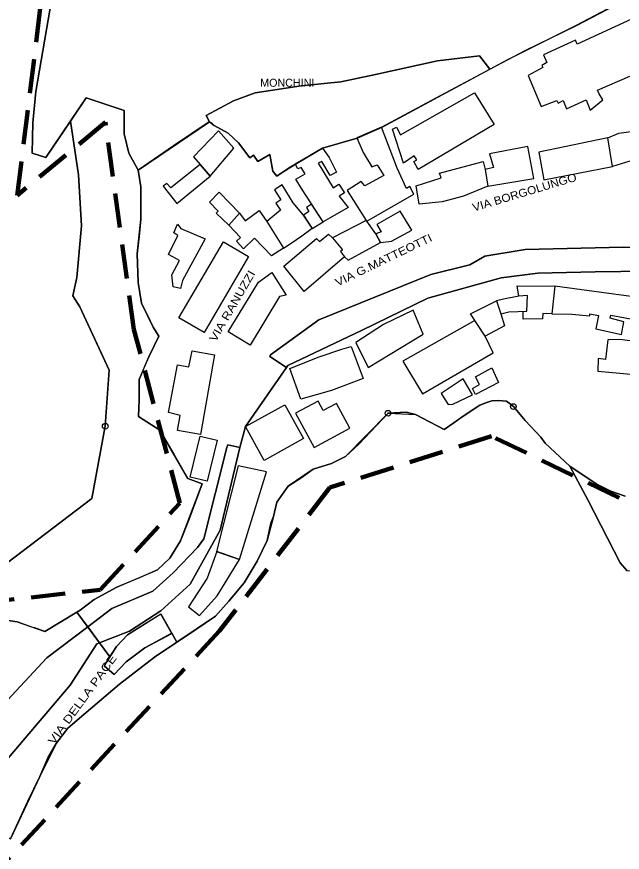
# Model space of a CAD drawing. Extents: x 654952 to 658955, y 890426 to 894481.
# Drawn here: x 657758 to 657969.7, y 890856.2 to 891148.5 of the extents above; entities that cross this region are included whole.
import ezdxf

# ---------------------------------------------------------------- set-up
doc = ezdxf.new("R2010")
doc.units = 0
doc.header["$LTSCALE"] = 4
doc.header["$PDMODE"] = 32
doc.header["$PDSIZE"] = 2
doc.linetypes.add('MEDIUM_DASHED', pattern=[4.5, 3, -1.5])
for name, color, linetype, lineweight in [('1', 7, 'Continuous', 25), ('16', 7, 'Continuous', 25), ('17', 7, 'Continuous', 25), ('35', 7, 'Continuous', 25), ('37', 7, 'Continuous', 25), ('4', 7, 'Continuous', 25), ('56', 7, 'Continuous', 25), ('7', 7, 'MEDIUM_DASHED', 100)]:
    doc.layers.add(name, color=color, linetype=linetype, lineweight=lineweight)
doc.layers.add('58', color=7, linetype='Continuous')

msp = doc.modelspace()

# ---------------------------------------------------------------- linework, layer by layer
at = {"layer": '1'}
for p, q in [((657931.64, 891012.14), (657935.76, 891007.24)), ((657779.02, 890940.19), (657782.81, 890935.06))]:
    msp.add_line(p, q, dxfattribs=at)
for points in [[(657968.84, 891153.47), (657953.43, 891145.35), (657929.55, 891133.41), (657923.52, 891130.17), (657904.52, 891120), (657885.62, 891109.84), (657877.08, 891106.06), (657864.89, 891102.58), (657853.22, 891095.62), (657848.96, 891092.72), (657847.55, 891094.49), (657846.53, 891100.27), (657842.34, 891097.91), (657840.84, 891100.05), (657839.5, 891099.17), (657835.5, 891104.36), (657835.5, 891104.36), (657831.88, 891107.74), (657827.04, 891110.49), (657826.49, 891111.1), (657825.32, 891111.72), (657812.77, 891103.29), (657800.42, 891094.89), (657801.42, 891089.02), (657801.4, 891083.36), (657801.38, 891077.71), (657800.76, 891071.65), (657800.14, 891065.59), (657800.42, 891055.53), (657801.6, 891048.25), (657803.68, 891044.08), (657805.75, 891039.92), (657807.7, 891036.7), (657804.18, 891029.55), (657802.49, 891025.6), (657800.8, 891021.65), (657800.86, 891014.36), (657800.72, 891011.53), (657800.58, 891008.7), (657808.09, 891003.92), (657812.96, 890995.46), (657817.82, 890987.01), (657822.78, 890985.06), (657818.2, 890972.48), (657815.25, 890965.19), (657813.41, 890962.16), (657811.56, 890959.13), (657807.21, 890955.06), (657801.13, 890952.28), (657792.95, 890948.9), (657785.05, 890944.65), (657780.21, 890940.92), (657779.02, 890940.19)], [(657968.84, 891153.47), (657953.43, 891145.35), (657929.55, 891133.41), (657923.52, 891130.17), (657904.52, 891120), (657885.62, 891109.84), (657877.08, 891106.06), (657864.89, 891102.58), (657853.22, 891095.62), (657848.96, 891092.72), (657847.55, 891094.49), (657846.53, 891100.27), (657842.34, 891097.91), (657840.84, 891100.05), (657839.5, 891099.17), (657835.5, 891104.36), (657835.5, 891104.36), (657831.88, 891107.74), (657827.04, 891110.49), (657826.49, 891111.1), (657825.32, 891111.72), (657812.77, 891103.29), (657800.42, 891094.89), (657801.42, 891089.02), (657801.4, 891083.36), (657801.38, 891077.71), (657800.76, 891071.65), (657800.14, 891065.59), (657800.42, 891055.53), (657801.6, 891048.25), (657803.68, 891044.08), (657805.75, 891039.92), (657807.7, 891036.7), (657804.18, 891029.55), (657802.49, 891025.6), (657800.8, 891021.65), (657800.86, 891014.36), (657800.72, 891011.53), (657800.58, 891008.7), (657808.09, 891003.92), (657812.96, 890995.46), (657817.82, 890987.01), (657822.78, 890985.06), (657818.2, 890972.48), (657815.25, 890965.19), (657813.41, 890962.16), (657811.56, 890959.13), (657807.21, 890955.06), (657801.13, 890952.28), (657792.95, 890948.9), (657785.05, 890944.65), (657780.21, 890940.92), (657779.02, 890940.19)], [(658007.35, 891066), (658005, 891066.21), (657992.69, 891067.61), (657970.1, 891067.87), (657935.78, 891067.08), (657921.68, 891064.73), (657916.45, 891061.72)], [(657916.45, 891061.72), (657921.68, 891064.73), (657935.78, 891067.08), (657970.1, 891067.87), (657992.69, 891067.61), (658005, 891066.21), (658007.35, 891066), (658011.76, 891065.61), (658011.88, 891065.59)], [(657916.45, 891061.72), (657902.74, 891058.33), (657863.58, 891042.52), (657846.73, 891030.24), (657846.45, 891029.65), (657852.37, 891025.82)], [(657846.45, 891029.65), (657846.73, 891030.24), (657863.58, 891042.52), (657902.74, 891058.33), (657916.45, 891061.72)], [(658005.48, 891057.35), (657996.08, 891059.77), (657960.31, 891059.25), (657940.21, 891058.85), (657927.42, 891057.15), (657901.7, 891050.1), (657878.59, 891038.73), (657852.74, 891026.46), (657852.37, 891025.82), (657837.96, 891005.1), (657836.03, 890997.85)], [(657927.42, 891057.15), (657940.21, 891058.85), (657960.31, 891059.25), (657996.08, 891059.77), (658005.48, 891057.35), (658005.67, 891057.34)], [(657852.37, 891025.82), (657852.74, 891026.46), (657878.59, 891038.73), (657901.7, 891050.1), (657927.42, 891057.15)], [(657836.03, 890997.85), (657837.96, 891005.1), (657852.37, 891025.82), (657846.45, 891029.65)], [(657887.82, 891009.79), (657897.41, 891009.34), (657907.44, 891004.07), (657914.14, 891008.82), (657919.98, 891012.56), (657922.07, 891013.46), (657924.16, 891014.15), (657926.4, 891014.25), (657929.21, 891013.96), (657931.64, 891012.14), (657935.76, 891007.24), (657941.25, 891001.37), (657942.82, 890999.28), (657951.45, 890991.3), (657960.64, 890985.14), (657965.69, 890982.49), (657970.77, 890980.82)], [(657910.79, 891006.44), (657914.34, 891008.96), (657919.98, 891012.56), (657922.07, 891013.46)], [(657922.07, 891013.46), (657924.16, 891014.15), (657926.4, 891014.25), (657929.21, 891013.96), (657931.64, 891012.14)], [(657796.67, 890932.22), (657808.36, 890939.56), (657813.94, 890929.67), (657816.98, 890931.7), (657827.5, 890938.75), (657832.14, 890944.06), (657837.47, 890950.5), (657842.1, 890958.08), (657845.58, 890965.22), (657846.89, 890971.28), (657847.8, 890973.67), (657848.97, 890978.63), (657852.94, 890984.24), (657857.78, 890987.42), (657861.69, 890990.21), (657868.08, 890992.2), (657872.98, 890994.64), (657877.63, 890998.94), (657887.82, 891009.79)], [(657872.98, 890994.64), (657887.82, 891009.79), (657894.16, 891010.12), (657897.41, 891009.34), (657907.44, 891004.07), (657910.79, 891006.44)], [(657935.76, 891007.24), (657941.25, 891001.37), (657942.82, 890999.28), (657951.45, 890991.3), (657960.64, 890985.14), (657965.69, 890982.49), (657970.77, 890980.82)], [(657831.86, 890998.71), (657831.46, 890997.86), (657823.37, 890965.86), (657821.17, 890962.87), (657812.66, 890954.01), (657805.53, 890947.58), (657791.3, 890941.51), (657782.81, 890935.06), (657786.92, 890929.49), (657790.73, 890930.97)], [(657782.81, 890935.06), (657791.3, 890941.51), (657805.53, 890947.58), (657812.66, 890954.01), (657821.17, 890962.87), (657823.37, 890965.86), (657831.46, 890997.86), (657831.86, 890998.71), (657836.03, 890997.85)], [(657836.03, 890997.85), (657829.11, 890968.86), (657818.67, 890950.04), (657808.35, 890940.63), (657797.39, 890933.58), (657790.73, 890930.97), (657786.92, 890929.49), (657790.57, 890924.54)], [(657790.73, 890930.97), (657797.39, 890933.58), (657808.35, 890940.63), (657818.67, 890950.04), (657829.11, 890968.86), (657836.03, 890997.85), (657831.86, 890998.71)], [(657848.97, 890978.63), (657852.94, 890984.24), (657861.69, 890990.21), (657868.08, 890992.2), (657872.98, 890994.64)], [(657813.94, 890929.67), (657827.5, 890938.75), (657832.14, 890944.06), (657837.47, 890950.5), (657842.1, 890958.08), (657845.58, 890965.22), (657846.89, 890971.28), (657847.8, 890973.67), (657848.97, 890978.63)], [(657725.36, 890877.89), (657732.97, 890886.13), (657768.49, 890924.18), (657782.81, 890935.06), (657779.02, 890940.19), (657767.79, 890933.42), (657764.28, 890934.69), (657763.67, 890934.84)], [(657781.51, 890904.42), (657793.93, 890915.04), (657806.13, 890924.44), (657813.95, 890929.67), (657812.18, 890932.8), (657802.73, 890927.7), (657796.29, 890922.88), (657792.09, 890918.38), (657788.54, 890921.42), (657790.57, 890924.54), (657779.02, 890940.19), (657767.79, 890933.42), (657764.28, 890934.69)], [(657779.02, 890940.19), (657790.57, 890924.54), (657792.83, 890928.2), (657796.67, 890932.22)], [(657763.67, 890934.84), (657758.11, 890936.83), (657752.75, 890937.58), (657752.55, 890936.55)], [(657764.28, 890934.69), (657763.67, 890934.84), (657758.11, 890936.83), (657752.75, 890937.58)], [(657574.37, 890754.32), (657578.26, 890754.88), (657589.68, 890761.22), (657613.14, 890780.87), (657703.81, 890839.21), (657730.45, 890856.96), (657740.58, 890872.18), (657758.97, 890893.74), (657776.73, 890914.66), (657786.02, 890929.14), (657786.92, 890929.49), (657782.81, 890935.06)], [(657782.81, 890935.06), (657768.49, 890924.18), (657732.97, 890886.13), (657725.36, 890877.89)], [(657813.95, 890929.67), (657812.18, 890932.8), (657802.73, 890927.7), (657796.29, 890922.88)], [(657802.73, 890927.7), (657812.18, 890932.8), (657813.94, 890929.67)], [(657786.92, 890929.49), (657786.02, 890929.14), (657776.73, 890914.66), (657758.97, 890893.74), (657740.58, 890872.18), (657730.45, 890856.96), (657703.81, 890839.21), (657613.14, 890780.87), (657589.68, 890761.22), (657578.26, 890754.88), (657574.37, 890754.32), (657576.43, 890745.94), (657582.96, 890734.36), (657592.26, 890723.72)], [(657796.29, 890922.88), (657792.09, 890918.38), (657788.54, 890921.42), (657790.56, 890924.56), (657786.92, 890929.49)], [(657790.57, 890924.54), (657788.54, 890921.42), (657792.09, 890918.38), (657796.29, 890922.88), (657802.73, 890927.7)], [(657793.93, 890915.04), (657806.13, 890924.44), (657813.95, 890929.67)], [(657722.39, 890830.85), (657734.26, 890840.22), (657740.54, 890846.62), (657752.72, 890862.46), (657755.86, 890860.94), (657761.88, 890874.11), (657766.09, 890882.69), (657768.92, 890889.28), (657771.75, 890894.27), (657775.9, 890899.63), (657781.51, 890904.42), (657793.93, 890915.04)], [(657719.11, 890828.65), (657725.5, 890832.95), (657734.26, 890840.22), (657740.54, 890846.62), (657746.63, 890853.99), (657752.72, 890862.46), (657755.86, 890860.94), (657761.88, 890874.11), (657766.09, 890882.69), (657768.92, 890889.28), (657771.75, 890894.27), (657775.9, 890899.63), (657781.51, 890904.42)]]:
    msp.add_lwpolyline(points, dxfattribs=at)
for p in [(657931.64, 891012.14), (657887.82, 891009.79)]:
    msp.add_point(p, dxfattribs=at)
at = {"layer": '16'}
for points in [[(657923.45, 891130.13), (657919.77, 891134.83), (657905.08, 891133.04), (657883.43, 891128.27), (657871.31, 891125.69), (657857.41, 891124.29), (657841.33, 891121.91), (657833.78, 891119.13), (657824.25, 891113.96), (657825.42, 891111.79), (657827.04, 891110.49)], [(657827.04, 891110.49), (657831.88, 891107.74), (657835.5, 891104.36), (657839.5, 891099.17), (657840.84, 891100.05), (657842.34, 891097.91), (657846.53, 891100.27), (657847.55, 891094.49), (657848.96, 891092.72), (657851.18, 891094.3), (657855.46, 891096.97), (657864.89, 891102.58), (657877.08, 891106.06), (657885.72, 891109.85), (657923.44, 891130.13)]]:
    msp.add_lwpolyline(points, dxfattribs=at)
at = {"layer": '17'}
for points in [[(657771.63, 891166.54), (657771.43, 891161.8), (657764.73, 891122.3), (657763.68, 891111.38), (657763.53, 891106.1), (657763.43, 891100.8), (657768.13, 891099.3), (657782.33, 891120.1), (657795.53, 891115.7), (657795.53, 891107.6), (657797.23, 891100.8), (657800.42, 891094.89), (657825.42, 891111.79)], [(657953.53, 891145.36), (657975.13, 891156.76), (657977.86, 891159.09), (657978.28, 891160.13), (657978.08, 891161.76)], [(657923.44, 891130.13), (657935.77, 891136.67), (657953.53, 891145.36)], [(657825.42, 891111.79), (657824.25, 891113.96), (657833.78, 891119.13), (657841.33, 891121.91), (657857.41, 891124.29), (657871.31, 891125.69), (657883.43, 891128.27), (657905.08, 891133.04), (657919.77, 891134.83), (657923.45, 891130.13)]]:
    msp.add_lwpolyline(points, dxfattribs=at)
at = {"layer": '35'}
for points in [[(657935.76, 891007.24), (657931.64, 891012.14), (657929.21, 891013.96), (657926.4, 891014.25), (657924.16, 891014.15), (657922.07, 891013.46), (657919.98, 891012.56), (657914.14, 891008.82), (657910.79, 891006.44)], [(657910.79, 891006.44), (657907.44, 891004.07), (657897.41, 891009.34), (657894.16, 891010.12), (657887.82, 891009.79), (657872.98, 890994.64), (657868.08, 890992.2), (657861.69, 890990.21), (657852.94, 890984.24), (657848.97, 890978.63), (657847.8, 890973.67), (657845.58, 890965.22), (657842.1, 890958.08), (657837.47, 890950.5), (657832.14, 890944.06), (657827.5, 890938.75), (657813.95, 890929.67), (657806.13, 890924.44), (657793.93, 890915.04), (657781.51, 890904.42), (657775.9, 890899.63), (657771.75, 890894.27), (657766.09, 890882.69), (657755.86, 890860.94)], [(658177.27, 890722.55), (658145.37, 890749.45), (658093.46, 890800.73), (658072.44, 890837.18), (658044.62, 890869.41), (658034.59, 890878.44), (658018.74, 890887.07), (658010.62, 890897.55), (658039.33, 890913.23), (658024.33, 890940.23), (658021.17, 890941.12), (658017.98, 890942.57), (658015.6, 890943.95), (658009.52, 890948.14), (658002.18, 890951.3), (657984.65, 890954.87), (657976.07, 890954.2), (657971.42, 890954.68), (657968.98, 890957.5), (657957.76, 890979.29), (657951.45, 890991.3), (657942.82, 890999.28), (657941.25, 891001.37), (657935.76, 891007.24)], [(657970.76, 890980.82), (657965.68, 890982.49), (657960.63, 890985.14), (657951.44, 890991.3), (657957.76, 890979.29), (657968.98, 890957.5), (657971.42, 890954.68)]]:
    msp.add_lwpolyline(points, dxfattribs=at)
at = {"layer": '37'}
for points in [[(657779.02, 890940.19), (657780.21, 890940.92), (657785.05, 890944.65), (657792.95, 890948.9), (657807.21, 890955.06), (657811.56, 890959.13), (657815.25, 890965.19), (657822.78, 890985.06), (657817.82, 890987.01), (657808.09, 891003.92), (657800.58, 891008.7), (657800.86, 891014.36), (657800.8, 891021.65), (657804.18, 891029.55), (657807.7, 891036.7), (657805.75, 891039.92), (657801.6, 891048.25), (657800.42, 891055.53), (657800.14, 891065.59), (657801.38, 891077.71), (657801.42, 891089.02), (657800.42, 891094.89), (657797.23, 891100.8), (657795.54, 891107.6), (657795.53, 891115.7), (657782.33, 891120.1), (657776.76, 891111.93), (657779.64, 891093.18)], [(657779.64, 891093.18), (657780.59, 891075.31), (657778.98, 891057.3), (657777.59, 891050.84), (657780.02, 891047.05), (657787.64, 891030.69)], [(657787.64, 891030.69), (657790.36, 891024.85), (657788.94, 891005.23)], [(657788.94, 891005.23), (657784.23, 890979.95), (657751.92, 890955.43), (657723.95, 890953.61), (657697.94, 890963.11), (657676.93, 890979.92), (657673.58, 890980.35), (657673.12, 890980.45), (657648.33, 890979.38), (657645.71, 890978.83), (657632.58, 890972.94), (657612, 890962.82), (657592, 890957.09), (657575.89, 890956.36), (657559.28, 890959.19), (657553.93, 890961.73), (657549.79, 890962.92), (657546.41, 890965.3)], [(657723.91, 890932.87), (657739.37, 890936.96), (657752.55, 890936.55), (657752.75, 890937.58), (657758.11, 890936.83), (657767.79, 890933.42), (657779.02, 890940.19)]]:
    msp.add_lwpolyline(points, dxfattribs=at)
msp.add_point((657788.94, 891005.23), dxfattribs=at)
at = {"layer": '4'}
msp.add_line((657958.41, 891044.52), (657961.39, 891044), dxfattribs=at)
for points in [[(657974.45, 891148.41), (657954.01, 891138.88), (657953.39, 891140.26), (657942.19, 891135.16), (657943.39, 891132.46), (657941.63, 891131.49), (657941.98, 891130.8), (657936.82, 891127.92), (657941.33, 891117.06), (657946.81, 891119.24), (657947.35, 891118.25), (657947.35, 891118.25), (657949.11, 891119.2), (657950.22, 891116.32), (657957.1, 891119.47), (657958.53, 891115.83), (657962.88, 891119.41), (657961.71, 891121.58), (657961.02, 891122.84), (657972.42, 891127.77)], [(657961.39, 891044), (657960.47, 891039.3), (657969.49, 891037.3), (657970.26, 891041.82), (657965.55, 891043), (657965.71, 891044.16), (657975.79, 891042.26), (657978.18, 891053.86), (657979.7, 891053.5), (657980.21, 891058.22), (657974.02, 891058.3), (657972.83, 891050.64), (657962.47, 891052.04), (657946.14, 891054.22), (657945.08, 891044.58), (657952.05, 891044.46), (657958.41, 891043.84), (657958.41, 891044.52)], [(657779.02, 890940.19), (657790.57, 890924.54), (657792.83, 890928.2), (657796.67, 890932.22), (657808.36, 890939.56), (657813.94, 890929.67)]]:
    msp.add_lwpolyline(points, dxfattribs=at)
for points in [[(657893.23, 891097.32), (657889.34, 891109.16), (657890.73, 891109.88), (657892.2, 891107.18), (657918.07, 891121.86), (657924.89, 891110.78), (657898.34, 891095.06), (657896.85, 891097.84), (657897.92, 891098.46), (657896.96, 891099.88)], [(657819.78, 891099.46), (657822.15, 891096.78), (657825.6, 891092.72), (657833.92, 891102.48), (657828.51, 891108.6)], [(657873.57, 891087.76), (657880.22, 891077.2), (657880.42, 891077.04), (657896.88, 891086.48), (657895.47, 891089.1), (657894.26, 891088.44), (657891.04, 891095.48), (657885.6, 891109.9), (657876.96, 891106.1), (657879.17, 891101.06), (657882.13, 891096.02), (657883.99, 891096.66), (657886.35, 891093.02), (657879.68, 891089.3), (657878.43, 891090.9)], [(657964.67, 891106.16), (657968.48, 891107.8), (657980.46, 891109.4), (657984.44, 891101.62), (657975.36, 891098.88), (657966.28, 891096.14)], [(657966.28, 891096.14), (657964.67, 891106.16), (657940.59, 891101.1), (657942.33, 891091.48)], [(657865.18, 891076.74), (657861.05, 891083.02), (657857.52, 891088.38), (657855.62, 891091.66), (657858.86, 891093.54), (657857.48, 891095.78), (657856.28, 891095.28), (657855.34, 891097.02), (657864.89, 891102.58), (657867.27, 891099.28), (657869.79, 891094.1), (657867.6, 891092.94), (657864.65, 891097.9), (657863.37, 891097.24), (657868.68, 891088.62), (657870.6, 891089.88), (657872.55, 891086.92), (657870.71, 891085.68), (657873.93, 891081.78), (657867.6, 891078.14)], [(657921.76, 891095.04), (657922.78, 891089.18), (657938.78, 891091.86), (657936.67, 891103.06), (657923.3, 891100.58), (657924.76, 891095.72)], [(657822.17, 891096.76), (657811.91, 891088.66), (657810.53, 891090.22), (657809.22, 891089.28), (657813.96, 891083.14), (657825.6, 891092.72)], [(657921.08, 891097.9), (657921.76, 891095.04), (657922.78, 891089.18), (657914.18, 891085.72), (657906.73, 891083.72), (657898.72, 891082.9), (657897.67, 891089.3), (657906.43, 891092.16), (657905.79, 891093.76)], [(657848.16, 891087.96), (657850.3, 891084.42), (657848.58, 891083.26), (657850.19, 891080.86), (657845.4, 891076.9), (657851.29, 891067.58), (657853.98, 891069.28), (657857.63, 891071.88), (657861.28, 891074.5), (657858.21, 891079.08), (657854.62, 891083.46), (657850.8, 891089.66)], [(657835.9, 891079.84), (657832.2, 891075.6), (657827.76, 891079.74), (657828.46, 891080.48), (657825.39, 891083.68), (657828.78, 891087.08), (657832.34, 891083.46)], [(657861.07, 891082.96), (657859.35, 891081.8), (657860.19, 891080.39), (657858.21, 891079.08), (657861.3, 891074.44), (657865.18, 891076.74)], [(657845.4, 891076.9), (657851.29, 891067.58), (657847.03, 891064.88), (657841.17, 891071), (657837.3, 891067.3), (657834.79, 891069.96), (657836.28, 891071.26), (657832.2, 891075.6), (657835.9, 891079.84), (657837.86, 891077.16), (657842.79, 891080.72)], [(657883.52, 891072.6), (657885.17, 891069.5), (657889.06, 891069.94), (657896.13, 891073.84), (657892.06, 891080.5), (657883.92, 891075.84), (657885.38, 891073.22)], [(657880.42, 891077.04), (657880.22, 891077.2), (657868.37, 891071.14), (657871.96, 891066.92), (657871.2, 891066.36), (657872.65, 891064.52), (657873.87, 891063.32), (657885.17, 891069.5), (657883.52, 891072.6)], [(657823.92, 891070.76), (657815.95, 891056.22), (657815.29, 891053.4), (657812.65, 891054.06), (657812.18, 891058.2), (657814.88, 891063.24), (657811.09, 891065.3), (657814.27, 891072), (657812.94, 891072.86), (657814.24, 891075.92), (657815.4, 891074.38)], [(657867.05, 891072.4), (657868.37, 891071.14), (657871.96, 891066.92), (657871.2, 891066.36), (657872.65, 891064.52), (657858.54, 891052.38), (657851.42, 891061.28), (657862.85, 891070.9), (657863.82, 891069.88)], [(657814.73, 891043.14), (657830.24, 891069.78), (657838.99, 891064.68), (657823.48, 891038.04)], [(657831.97, 891038.28), (657842.48, 891055.66), (657847.23, 891059), (657852.22, 891051.14), (657849.9, 891050.68), (657839.57, 891033.64)], [(657933.54, 891050.74), (657933, 891054.4), (657946.14, 891054.22), (657945.08, 891044.58), (657941.95, 891044.7), (657941.85, 891042.86), (657935.12, 891042.66), (657935.09, 891045.42), (657936.37, 891045.46), (657936.6, 891050.96)], [(657925.73, 891049.12), (657927.23, 891044.62), (657930.02, 891045.28), (657936.37, 891045.46), (657936.6, 891050.96), (657933.54, 891050.74), (657928.25, 891049.72)], [(657925.73, 891049.12), (657927.23, 891044.62), (657928.54, 891040.32), (657921.78, 891036.76), (657916.7, 891044.58)], [(657876.55, 891034.6), (657880.9, 891025.82), (657900.14, 891037.4), (657896.56, 891045.88), (657886.24, 891040.86)], [(657918.23, 891042.26), (657893.04, 891028.04), (657899.86, 891016.62), (657924.63, 891030.98), (657921.78, 891036.76)], [(657964.64, 891035.5), (657963.9, 891028.6), (657961.25, 891028.94), (657961.22, 891024.54), (657977.86, 891023.04), (657978.59, 891026.58), (657986.31, 891026.18), (657986.31, 891022.62), (657998.58, 891020.24), (658001.09, 891035.58), (657996.11, 891035.12), (657975.09, 891036.58), (657975.12, 891034.78), (657968.91, 891035.58)], [(657853.54, 891025.46), (657863.8, 891029.56), (657871.67, 891032.26), (657874.95, 891033.2), (657879.08, 891021.98), (657868.03, 891017.8), (657857.28, 891014.68)], [(657827.13, 891030.22), (657822.24, 891002.34), (657814.21, 891003.72), (657815.18, 891009.06), (657811.06, 891010), (657814.24, 891026.7), (657818.2, 891026.06), (657819.29, 891031.58)], [(657918.43, 891022.48), (657924.11, 891025.64), (657926.46, 891020.54), (657918.4, 891016.32), (657917.31, 891018.46), (657919.76, 891019.82)], [(657906.38, 891016.72), (657908.84, 891012.82), (657910.46, 891012.98), (657917.42, 891016.24), (657914.11, 891021.84)], [(657837.96, 891005.1), (657851.74, 891012.76), (657858.32, 891000.9), (657844.54, 890993.26)], [(657855.5, 891009.78), (657861.97, 890997.78), (657874.48, 891004.54), (657869.79, 891013.24), (657865.16, 891010.74), (657863.38, 891014.02)], [(657828.05, 891000.32), (657824.62, 890986.06), (657818.68, 890987.48), (657822.11, 891001.76)], [(657835.45, 890991.38), (657827.9, 890961.48), (657835.91, 890958.62), (657845.36, 890989.28)], [(657827.92, 890961.43), (657824.54, 890952.15), (657818.08, 890942.12), (657821.85, 890939.09), (657828.09, 890945.89), (657835.91, 890958.6)], [(657788.54, 890921.42), (657792.09, 890918.38), (657796.29, 890922.88), (657802.73, 890927.7), (657812.2, 890932.75), (657808.38, 890939.5), (657796.67, 890932.22), (657792.85, 890928.14)]]:
    msp.add_lwpolyline(points, close=True, dxfattribs=at)
at = {"layer": '56'}
for points in [[(657776.76, 891111.93), (657768.13, 891099.3), (657763.43, 891100.8), (657763.53, 891106.1), (657763.68, 891111.38), (657764.73, 891122.3), (657771.43, 891161.8), (657771.63, 891166.54), (657772.9, 891179.23), (657772.91, 891189.31), (657772.9, 891199.43), (657773.74, 891205.98), (657776.21, 891212.12), (657780.73, 891220.2)], [(657751.92, 890955.43), (657784.23, 890979.95), (657788.94, 891005.23), (657790.36, 891024.85), (657780.02, 891047.05), (657777.59, 891050.84), (657778.98, 891057.3), (657780.59, 891075.31), (657779.64, 891093.18), (657776.76, 891111.93)]]:
    msp.add_lwpolyline(points, dxfattribs=at)
at = {"layer": '7'}
msp.add_lwpolyline([(658184.33, 890889.29), (658123.56, 891003.8), (657984.81, 890972.39), (657924.04, 891001.78), (657867.48, 890983.79), (657828.91, 890933.62), (657730.13, 890826.94), (657605.09, 890761.67), (657625.78, 890734.22), (657633.49, 890699.48), (657619.39, 890680.55), (657581.42, 890722.64), (657563.43, 890772.81), (657526.14, 890797.25), (657562.14, 890822.34), (657553.14, 890879.58), (657603.92, 890886.02), (657709.35, 890939.4), (657787.21, 890948.05), (657815.02, 890978.31), (657798.98, 891039.09), (657789.02, 891111.62), (657758.18, 891086.01), (657767.85, 891164.67)], dxfattribs=at)

# ---------------------------------------------------------------- texts
at = {"layer": '58'}
msp.add_text('MONCHINI', height=2.801, dxfattribs=at).set_placement((657843.13, 891124.01))
for s, height, rotation, width, p in [('VIA BORGOLUNGO', 2.802, 16.692, 1.1, (657917.84, 891080.32)), ('VIA G.MATTEOTTI', 2.799, 25.814, 1.15, (657870.19, 891054.06)), ('VIA RANUZZI', 2.797, 59.997, 1.2, (657827.59, 891034.53)), ('VIA DELLA PACE', 2.802, 53.961, 1.25, (657770.95, 890893.59))]:
    msp.add_text(s, height=height, rotation=rotation, dxfattribs=dict(at, width=width)).set_placement(p)

doc.saveas('drawing.dxf')
